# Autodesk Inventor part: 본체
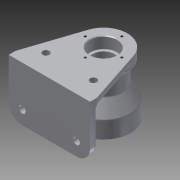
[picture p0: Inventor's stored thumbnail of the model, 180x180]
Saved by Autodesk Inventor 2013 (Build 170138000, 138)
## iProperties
Created: 2015-07
Part Number: 본체
Material: 알루미늄 6061
Document SubType Name: Modeling
Designer: user
Density: 2.71 g/cm^3
Mass: 1056.5 g
Surface Area: 738.517 cm^2
Volume: 389.853 cm^3
Author: user
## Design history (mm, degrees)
sketch "스케치1"
  geometry: L1 (-60, -40)-(60, -40); L2 (60, -40)-(60, 40); L3 (60, 40)-(-60, 40); L4 (-60, 40)-(-60, -40); 3 further points
  constraints: 8 end point, 2 midpoint, 2 parallel, 1 horizontal, 1 horizontal alignment, 1 perpendicular, 1 vertical alignment
  dimensions: "d0" = 120 distance of L3.end L2.end; "d1" = 80 distance of L2.end L1.end
extrude "돌출1" new body sketch "스케치1" distance "d2" = 10; taper "d3" = 0 deg
fillet "모깎기1" dims "d4" = 20
sketch "스케치2"
  geometry: A1 r 20 centre (-40, -20) between (-60, -20) and (-40, -40) reference; A2 r 20 centre (40, -20) between (40, -40) and (60, -20) reference; 1 further point
hole "구멍1" sketch "스케치2" at (-40, -20), (40, -20) diameter "d7" = 10; stored, may be unused: countersink angle "d11" = 90 deg, drill point angle "d13" = 118 deg; dims "d8" = 6, "d9" = 4, "d10" = 2, "d12" = 8
sketch "스케치5"
  geometry: L1 (0, 0)-(0, 10) reference; L2 (60, 0)-(60, 80); L3 (60, 0)-(140, 0); C1 r 35 at (60, 80)
  constraints: 4 end point, 1 centre point, 1 coincident, 1 horizontal, 1 parallel, 1 perpendicular
  dimensions: "d15" = 80 distance of L2.start L2.end; "d16" = 90 deg angle of L3 L2 (derived); "d17" = 70 diameter of C1
extrude "돌출2" join sketch "스케치5" distance "d18" = 15; taper "d19" = 0 deg
sketch "스케치6"
  geometry: C1 r 35 at (0, 0) reference; C2 r 28 at (0, 0); 1 further point
  constraints: 1 centre point, 1 coincident
  dimensions: "d20" = 56 diameter of C2
extrude "돌출3" join sketch "스케치6" distance "d21" = 50; taper "d22" = 0 deg
sketch "스케치7"
  geometry: C1 r 28 at (0, 0) reference; C2 r 40 at (0, 0); 1 further point
  constraints: 1 centre point, 1 coincident
  dimensions: "d23" = 80 diameter of C2
extrude "돌출4" join sketch "스케치7" distance "d24" = 25; taper "d25" = 0 deg
node "작업 평면1"
sketch "스케치8"
  geometry: L1 (-80, 0)-(-80, 10) reference; L2 (-80, 10)-(0, 10) reference; L3 (0, 10)-(0, 0) reference; L4 (0, 0)-(-80, 0) reference; L5 (0, 45)-(-15, 45) reference; L6 (-15, 45)-(-15, 52) reference; L7 (-15, 52)-(-65, 52) reference; L8 (-65, 52)-(-65, 40) reference; L9 (-65, 40)-(-90, 40) reference; L10 (-90, 40)-(-90, 52) reference; L11 (-90, 52)-(-65, 52) reference; L12 (0, 115)-(0, 45) reference; L13 (-15, 115)-(0, 115) reference; L14 (-15, 108)-(-15, 115) reference; L15 (-65, 108)-(-15, 108) reference; L16 (-65, 52)-(-65, 108) reference; L17 (-65, 120)-(-65, 108) reference; L18 (-65, 108)-(-90, 108) reference; L19 (-90, 108)-(-90, 120) reference; L20 (-90, 120)-(-65, 120) reference; L21 (-65, 120)-(-44.215, 108); L22 (-65, 120)-(-33.006, 120); L23 (-65, 80)-(0, 80); L24 (-15, 115)-(-20.874, 108); L25 (-15, 115)-(3.276, 115); L26 (-65, 120)-(-65, 108); L27 (-65, 108)-(-44.215, 108); L28 (-20.874, 108)-(-15, 108); L29 (-15, 115)-(-15, 108); 1 further point
  constraints: 18 end point, 3 collinear, 2 horizontal, 2 midpoint, 2 point on line, 1 parallel
  dimensions: "d26" = 30 deg angle of L21 L22; "d27" = 130 deg angle of L24 L25
revolve "회전1" sketch "스케치8" stored, may be unused: angle "d28" = 90 deg
sketch "스케치9"
  geometry: C1 r 28 at (0, 0) reference; 1 further point
extrude "돌출5" join sketch "스케치9" distance "d29" = 25; taper "d30" = 0 deg
sketch "스케치10"
  geometry: C1 r 40 at (0, 0) reference; C2 r 16 at (0, 0); 1 further point
  constraints: 1 centre point, 1 coincident
  dimensions: "d32" = 32 diameter of C2
hole "구멍2" sketch "스케치10" at (0, 0) diameter "d33" = 32; stored, may be unused: countersink angle "d37" = 90 deg, drill point angle "d39" = 118 deg; dims "d34" = 6, "d35" = 4, "d36" = 2, "d38" = 8
sketch "스케치11"
  geometry: C1 r 16 at (0, 0) reference; C2 r 40 at (0, 0) reference; C3 r 20 at (0, 0); 1 further point
  constraints: 1 centre point, 1 coincident
  dimensions: "d40" = 40 diameter of C3
extrude "돌출6" cut sketch "스케치11" distance "d41" = 23; taper "d42" = 0 deg
sketch "스케치12"
  geometry: C1 r 20 at (0, 0) reference; C2 r 40 at (0, 0) reference; C3 r 26 at (0, 0); 1 further point
  constraints: 1 centre point, 1 coincident
  dimensions: "d43" = 52 diameter of C3
extrude "돌출7" cut sketch "스케치12" distance "d44" = 20; taper "d45" = 0 deg
fillet "모깎기3" dims "d46" = 3
sketch "스케치13"
  geometry: C1 r 16 at (0, 0) reference; C2 r 35 at (0, 0) reference; C3 r 20 at (0, 0); 1 further point
  constraints: 1 centre point, 1 coincident
  dimensions: "d47" = 40 diameter of C3
extrude "돌출8" cut sketch "스케치13" distance "d48" = 17; taper "d49" = 0 deg
chamfer "모따기1" distance "d50" = 1; stored, may be unused: second distance "d51" = 2, angle "d52" = 30 deg
fillet "모깎기4" dims "d53" = 0.3
sketch "스케치14"
  geometry: L1 (0, 10)-(120, 10) reference; L2 (120, 10)-(120, 0) reference; L3 (120, 0)-(0, 0) reference; L4 (0, 0)-(0, 10) reference; L5 (120, 10)-(93.232, 90.984); L6 (26.768, 90.984)-(0, 10); L7 (26.768, 90.984)-(46.091, 55.349); L8 (46.091, 55.349)-(76.501, 55.349); L9 (76.501, 55.349)-(93.232, 90.984); L10 (0, 10)-(2.711, 5); L11 (2.711, 5)-(115.451, 5); L12 (115.451, 5)-(120, 10); C1 r 21 at (60, 80) reference; A1 r 35 centre (60, 80) between (93.232, 90.984) and (26.768, 90.984) reference; 1 further point
  constraints: 16 end point, 2 parallel, 2 point on circle, 2 tangent, 1 perpendicular
  dimensions: "d54" = 42.2947 deg angle of L2 L12; "d55" = 64.8505 deg angle of L3 L9; "d56" = 61.5314 deg angle of L3 L7; "d57" = 55.34911 distance between parallel lines of L3 L8; "d58" = 5 distance between parallel lines of L3 L11
extrude "돌출9" join sketch "스케치14" distance "d59" = 10; taper "d60" = 0 deg
node "작업 평면2"
sketch "스케치15"
  geometry: L1 (-5, 120)-(15.785, 108) reference; L2 (15.785, 108)-(39.126, 108) reference; L3 (39.126, 108)-(45, 115) reference; L4 (45, 115)-(60, 115) reference; L5 (60, 115)-(60, 101) reference; L6 (60, 101)-(59, 100) reference; L7 (59, 100)-(43.3, 100) reference; L8 (43, 99.7)-(43, 96) reference; L9 (43, 96)-(-7, 96) reference; L10 (-7, 96)-(-7, 97) reference; L11 (-10, 100)-(-10, 105.7) reference; L12 (-10.3, 106)-(-29, 106) reference; L13 (-29, 106)-(-30, 107) reference; L14 (-30, 107)-(-30, 120) reference; L15 (-30, 120)-(-5, 120) reference; L16 (15.785, 52)-(-5, 40) reference; L17 (-5, 40)-(-30, 40) reference; L18 (-30, 40)-(-30, 53) reference; L19 (-30, 53)-(-29, 54) reference; L20 (-29, 54)-(-10.3, 54) reference; L21 (-10, 54.3)-(-10, 60) reference; L22 (-7, 63)-(-7, 64) reference; L23 (-7, 64)-(43, 64) reference; L24 (43, 64)-(43, 60.3) reference; L25 (43.3, 60)-(59, 60) reference; L26 (59, 60)-(60, 59) reference; L27 (60, 59)-(60, 0) reference; L28 (60, 0)-(-20, 0) reference; L29 (-20, 0)-(-20, 10) reference; L30 (-20, 10)-(50, 10) reference; L31 (50, 10)-(50, 45) reference; L32 (50, 45)-(45, 45) reference; L33 (45, 45)-(39.126, 52) reference; L34 (39.126, 52)-(15.785, 52) reference; L35 (-20, 10)-(-3, 10); L36 (-3, 10)-(-23.207, 45); L37 (-23.207, 45)-(9.486, 57.15); L38 (9.486, 57.15)-(45, 57.15); L39 (45, 57.15)-(54.902, 40); L40 (54.902, 40)-(54.902, 5); L41 (54.902, 5)-(-3, 5); L42 (-3, 5)-(-3, 10); A1 r 0.3 centre (43.3, 99.7) between (43.3, 100) and (43, 99.7) reference; A2 r 3 centre (-10, 97) between (-7, 97) and (-10, 100) reference; A3 r 0.3 centre (-10.3, 105.7) between (-10, 105.7) and (-10.3, 106) reference; A4 r 0.3 centre (-10.3, 54.3) between (-10.3, 54) and (-10, 54.3) reference; A5 r 3 centre (-10, 63) between (-10, 60) and (-7, 63) reference; A6 r 0.3 centre (43.3, 60.3) between (43, 60.3) and (43.3, 60) reference; 1 further point
  constraints: 16 end point, 4 parallel, 1 perpendicular, 1 point on line
  dimensions: "d61" = 17 distance of L29.end L35.end; "d62" = 60 deg angle of L36 L35; "d63" = 110.387 deg angle of L5 L37; "d64" = 5.09844 distance between parallel lines of L5 L40; "d65" = 57.15 distance between parallel lines of L28 L38; "d66" = 5 distance between parallel lines of L28 L41; "d67" = 65.14422 distance between parallel lines of L39 L36; "d68" = 36.6292 distance from line of L4.end L37
extrude "돌출10" join sketch "스케치15" stored distance "d69" = 10; taper "d70" = 0 deg
fillet "모깎기6" dims "d72" = 5
fillet "모깎기7" dims "d73" = 3
fillet "모깎기8" dims "d74" = 3
sketch "스케치16"
  geometry: L1 (0, 0)-(120, 0) reference; L2 (0, 0)-(25, 0); L3 (25, 0)-(25, 30); L4 (25, 30)-(95, 30); C1 r 5 at (25, 30); C2 r 5 at (95, 30); 1 further point
  constraints: 6 end point, 2 centre point, 2 coincident, 1 parallel, 1 perpendicular, 1 point on line
  dimensions: "d76" = 25 distance of L1.start L2.end; "d77" = 30 distance of L2.end L3.end; "d78" = 70 distance of L3.end L4.end; "d79" = 90 deg angle of L3 L4 (derived); "d80" = 10 diameter of C1; "d81" = 10 diameter of C2
extrude "돌출11" cut sketch "스케치16" distance "d82" = 10; taper "d83" = 0 deg
sketch "스케치17"
  geometry: C1 r 27 at (0, 0) reference; A1 r 33 centre (0, 0) between (33, 0) and (0, 33); 3 further points
  constraints: 4 point on circle, 1 centre point, 1 coincident
  dimensions: "d84" = 66 diameter of A1
hole "구멍3" sketch "스케치17" at (33, 0), (0, 33), (-33, 0), (0, -33) diameter "d85" = 3.459; stored, may be unused: countersink angle "d89" = 82 deg, drill point angle "d91" = 118 deg; dims "d86" = 10, "d87" = 3.023, "d88" = 2, "d90" = 13
sketch "스케치18"
  geometry: C1 r 21 at (60, 80) reference; A1 r 27 centre (60, 80) between (87, 80) and (60, 107); 3 further points
  constraints: 4 point on circle, 1 centre point, 1 coincident
  dimensions: "d92" = 54 diameter of A1
hole "구멍4" sketch "스케치18" at (87, 80), (60, 107), (33, 80), (60, 53) diameter "d93" = 3.459; stored, may be unused: countersink angle "d97" = 82 deg, drill point angle "d99" = 118 deg; dims "d94" = 10, "d95" = 3.023, "d96" = 2, "d98" = 13
sketch "스케치19"
  geometry: L1 (-40, 40)-(40, 40) reference; L2 (60, 20)-(60, -30) reference; L3 (60, -30)-(60, -40) reference; L4 (60, -40)-(-60, -40) reference; L5 (-60, -40)-(-60, -30) reference; L6 (-60, -30)-(-60, 20) reference; L7 (5, -30)-(60, -30) reference; L8 (5, 17.226)-(5, -30) reference; L9 (-5, -30)-(-5, 17.226) reference; L10 (-60, -30)-(-5, -30) reference; L11 (-40, 40)-(40, 40) reference; L12 (60, 20)-(60, -30) reference; L13 (60, -30)-(60, -40) reference; L14 (60, -40)-(-60, -40) reference; L15 (-60, -40)-(-60, -30) reference; L16 (-60, -30)-(-60, 20) reference; L17 (5, -30)-(60, -30) reference; L18 (5, 17.226)-(5, -30) reference; L19 (-5, -30)-(-5, 17.226) reference; L20 (-60, -30)-(-5, -30) reference; C1 r 5 at (-40, 20) reference; C2 r 5 at (40, 20) reference; C3 r 5 at (-40, 20) reference; C4 r 5 at (40, 20) reference; C5 r 5 at (-40, 20) reference; C6 r 5 at (40, 20) reference; A1 r 20 centre (-40, 20) between (-40, 40) and (-60, 20) reference; A2 r 20 centre (40, 20) between (60, 20) and (40, 40) reference; A3 r 20 centre (-40, 20) between (-40, 40) and (-60, 20) reference; A4 r 20 centre (40, 20) between (60, 20) and (40, 40) reference; 7 further points; 2 other entities
  constraints: 4 other
feature "엠보싱1" sketch "스케치19" dims "d103" = 0.5, "d104" = 0
sketch "스케치20"
  geometry: L1 (-59.961, -40)-(-34.961, -40); L2 (-34.961, -40)-(-34.961, -15); L3 (-40, 40)-(40, 40) reference; L4 (60, 20)-(60, -30) reference; L5 (60, -30)-(60, -40) reference; L6 (60, -40)-(-60, -40) reference; L7 (-60, -40)-(-60, -30) reference; L8 (-60, -30)-(-60, 20) reference; L9 (5, -30)-(60, -30) reference; L10 (5, 17.226)-(5, -30) reference; L11 (-5, -30)-(-5, 17.226) reference; L12 (-60, -30)-(-5, -30) reference; C1 r 5 at (-40, 20) reference; C2 r 5 at (40, 20) reference; A1 r 20 centre (-40, 20) between (-40, 40) and (-60, 20) reference; A2 r 20 centre (40, 20) between (60, 20) and (40, 40) reference; 3 further points; 1 other entity
  constraints: 4 end point, 1 coincident, 1 perpendicular, 2 other
  dimensions: "d105" = 25 distance of L1.start L1.end; "d106" = 25 distance of L1.end L2.end
feature "엠보싱2" sketch "스케치20" dims "d107" = 0.5, "d108" = 0
sketch "스케치21"
  geometry: C1 r 27 at (0, 0) reference; C2 r 27 at (0, 0); 1 further point
  constraints: 1 centre point, 1 coincident, 1 concentric
extrude "돌출12" cut sketch "스케치21" stored distance "d109" = 0; taper "d110" = 0 deg
sketch "스케치22"
  geometry: C1 r 27 at (0, 0) reference; C2 r 27 at (0, 0); 1 further point
  constraints: 1 centre point, 1 coincident, 1 concentric
extrude "돌출13" join sketch "스케치22" distance "d111" = 90; taper "d112" = 0 deg
sketch "스케치23"
  geometry: C1 r 40 at (0, 0) reference; C2 r 16 at (0, 0); 1 further point
  constraints: 1 centre point, 1 coincident
  dimensions: "d113" = 32 diameter of C2
extrude "돌출14" cut sketch "스케치23" distance "d114" = 90; taper "d115" = 0 deg
sketch "스케치24"
  geometry: C1 r 16 at (0, 0) reference; C2 r 40 at (0, 0) reference; C3 r 20 at (0, 0); 1 further point
  constraints: 1 centre point, 1 coincident
  dimensions: "d116" = 40 diameter of C3
extrude "돌출15" cut sketch "스케치24" distance "d117" = 23; taper "d118" = 0 deg
sketch "스케치25"
  geometry: C1 r 20 at (0, 0) reference; C2 r 40 at (0, 0) reference; C3 r 26 at (0, 0); 1 further point
  constraints: 1 centre point, 1 coincident
  dimensions: "d119" = 52 diameter of C3
extrude "돌출16" cut sketch "스케치25" distance "d120" = 20; taper "d121" = 0 deg
sketch "스케치26"
  geometry: C1 r 16 at (60, 80) reference; C2 r 20 at (60, 80); A1 r 35 centre (60, 80) between (93.232, 90.984) and (26.768, 90.984) reference; 1 further point
  constraints: 1 centre point, 1 coincident
  dimensions: "d122" = 40 diameter of C2
extrude "돌출17" cut sketch "스케치26" distance "d123" = 17; taper "d124" = 0 deg
sketch "스케치27"
  geometry: A1 r 1.73 centre (60, 107) between (61.729, 106.945) and (58.271, 106.945) reference; A2 r 1.73 centre (87, 80) between (86.945, 78.271) and (86.945, 81.729) reference; A3 r 1.73 centre (33, 80) between (33.055, 81.729) and (33.055, 78.271) reference; A4 r 1.73 centre (60, 53) between (58.271, 53.055) and (61.729, 53.055) reference; 5 further points
  constraints: 4 coincident
hole "구멍5" sketch "스케치27" at (33, 80), (60, 107), (87, 80), (60, 53) diameter "d125" = 3.459; stored, may be unused: countersink angle "d129" = 82 deg, drill point angle "d131" = 118 deg; dims "d126" = 10, "d127" = 3.023, "d128" = 2, "d130" = 13
chamfer "모따기2" distance "d132" = 1; stored, may be unused: second distance "d133" = 2, angle "d134" = 30 deg
fillet "모깎기10" dims "d135" = 0.3
fillet "모깎기11" dims "d136" = 3
fillet "모깎기12" dims "d137" = 3
fillet "모깎기13" dims "d138" = 3
fillet "모깎기14" dims "d139" = 3
fillet "모깎기15" dims "d140" = 3
node "솔리드1"
node "절단 모서리 투영1"
node "절단 모서리 투영2"
node "절단 모서리 투영3"
node "절단 모서리 투영4"
node "절단 모서리 투영5"
node "절단 모서리 투영6"
